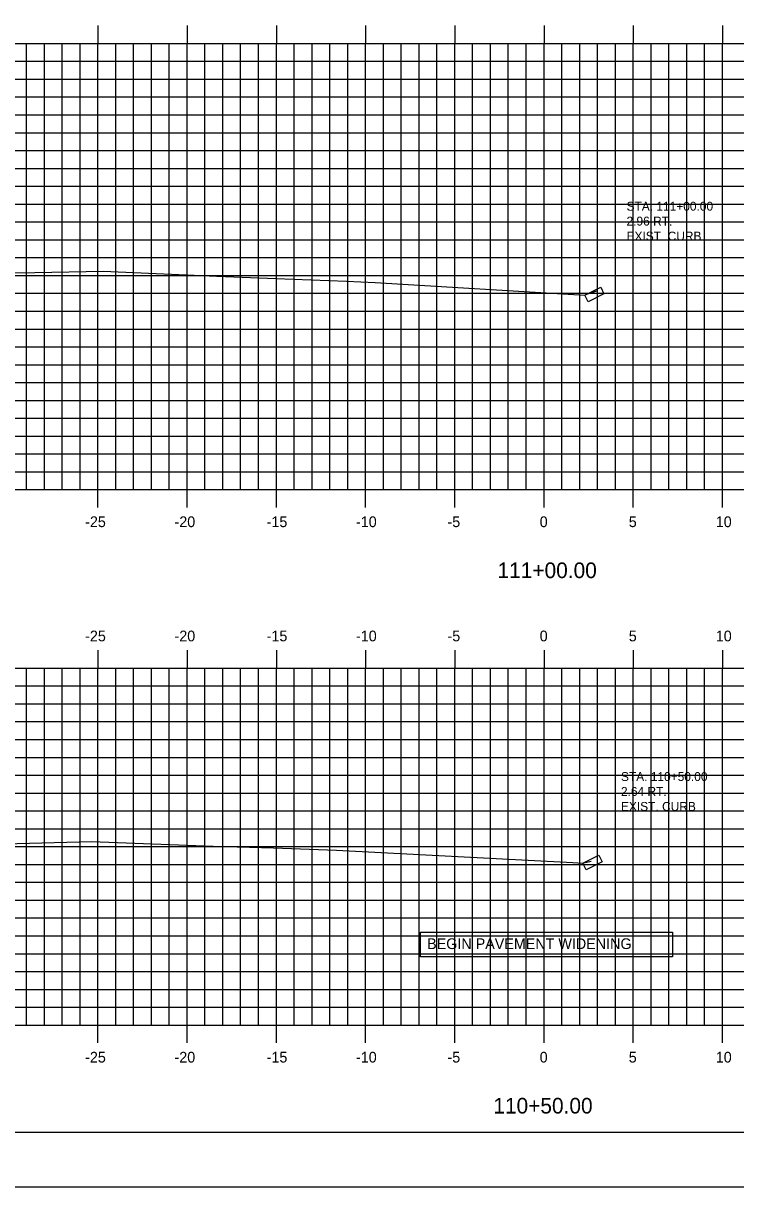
# Model space of a CAD drawing. Extents: x 1668473 to 1668643, y 337823 to 337933.
# Drawn here: x 1668526.6 to 1668566.5, y 337823.4 to 337888.6 of the extents above; entities that cross this region are included whole.
import ezdxf

# ---------------------------------------------------------------- set-up
doc = ezdxf.new("R2010")
doc.units = 0
for name, color, linetype in [('ANNOTATION', 7, 'Continuous'), ('BORDER', 7, 'Continuous'), ('D_Text_Monospaced', 7, 'Continuous'), ('H_V ANNOTATION', 7, 'Continuous'), ('MAJOR', 7, 'Continuous'), ('MINOR', 7, 'Continuous'), ('PLOT BOUNDARY', 7, 'Continuous'), ('S_Curb_Type_5', 7, 'Continuous'), ('S_Roadway_Centerline', 7, 'Continuous')]:
    doc.layers.add(name, color=color, linetype=linetype)

msp = doc.modelspace()

# ---------------------------------------------------------------- linework, layer by layer
at = {"layer": 'ANNOTATION'}
msp.add_lwpolyline([(1668548.868, 337837.666), (1668562.977, 337837.666), (1668562.977, 337836.276), (1668548.868, 337836.276)], close=True, dxfattribs=at)
at = {"layer": 'BORDER'}
msp.add_line((1668480.786, 337826.453), (1668640.786, 337826.453), dxfattribs=at)
at = {"layer": 'MAJOR'}
for p, q in [((1668530.785, 337888.455), (1668530.785, 337887.453)), ((1668535.785, 337888.455), (1668535.785, 337887.453)), ((1668540.785, 337888.455), (1668540.785, 337887.453)), ((1668545.785, 337888.455), (1668545.785, 337887.453)), ((1668550.785, 337888.455), (1668550.785, 337887.453)), ((1668555.785, 337888.455), (1668555.785, 337887.453)), ((1668560.785, 337888.455), (1668560.785, 337887.453)), ((1668565.785, 337888.455), (1668565.785, 337887.453)), ((1668485.785, 337887.453), (1668625.785, 337887.453)), ((1668485.785, 337887.453), (1668625.785, 337887.453)), ((1668530.785, 337862.453), (1668530.785, 337887.453)), ((1668535.785, 337862.453), (1668535.785, 337887.453)), ((1668540.785, 337862.453), (1668540.785, 337887.453)), ((1668545.785, 337862.453), (1668545.785, 337887.453)), ((1668550.785, 337862.453), (1668550.785, 337887.453)), ((1668555.785, 337862.453), (1668555.785, 337887.453)), ((1668560.785, 337862.453), (1668560.785, 337887.453)), ((1668565.785, 337862.453), (1668565.785, 337887.453)), ((1668485.785, 337882.453), (1668625.785, 337882.453)), ((1668485.785, 337877.453), (1668625.785, 337877.453)), ((1668485.785, 337872.453), (1668625.785, 337872.453)), ((1668485.785, 337867.453), (1668625.785, 337867.453)), ((1668485.785, 337862.453), (1668625.785, 337862.453)), ((1668485.785, 337862.453), (1668625.785, 337862.453)), ((1668530.785, 337861.451), (1668530.785, 337862.453)), ((1668535.785, 337861.451), (1668535.785, 337862.453)), ((1668540.785, 337861.451), (1668540.785, 337862.453)), ((1668545.785, 337861.451), (1668545.785, 337862.453)), ((1668550.785, 337861.451), (1668550.785, 337862.453)), ((1668555.785, 337861.451), (1668555.785, 337862.453)), ((1668560.785, 337861.451), (1668560.785, 337862.453)), ((1668565.785, 337861.451), (1668565.785, 337862.453)), ((1668530.785, 337853.455), (1668530.785, 337852.453)), ((1668535.785, 337853.455), (1668535.785, 337852.453)), ((1668540.785, 337853.455), (1668540.785, 337852.453)), ((1668545.785, 337853.455), (1668545.785, 337852.453)), ((1668550.785, 337853.455), (1668550.785, 337852.453)), ((1668555.785, 337853.455), (1668555.785, 337852.453)), ((1668560.785, 337853.455), (1668560.785, 337852.453)), ((1668565.785, 337853.455), (1668565.785, 337852.453)), ((1668485.785, 337852.453), (1668625.785, 337852.453)), ((1668485.785, 337852.453), (1668625.785, 337852.453)), ((1668530.785, 337832.453), (1668530.785, 337852.453)), ((1668535.785, 337832.453), (1668535.785, 337852.453)), ((1668540.785, 337832.453), (1668540.785, 337852.453)), ((1668545.785, 337832.453), (1668545.785, 337852.453)), ((1668550.785, 337832.453), (1668550.785, 337852.453)), ((1668555.785, 337832.453), (1668555.785, 337852.453)), ((1668560.785, 337832.453), (1668560.785, 337852.453)), ((1668565.785, 337832.453), (1668565.785, 337852.453)), ((1668485.785, 337847.453), (1668625.785, 337847.453)), ((1668485.785, 337842.453), (1668625.785, 337842.453)), ((1668485.785, 337837.453), (1668625.785, 337837.453)), ((1668485.785, 337832.453), (1668625.785, 337832.453)), ((1668485.785, 337832.453), (1668625.785, 337832.453)), ((1668530.785, 337831.451), (1668530.785, 337832.453)), ((1668535.785, 337831.451), (1668535.785, 337832.453)), ((1668540.785, 337831.451), (1668540.785, 337832.453)), ((1668545.785, 337831.451), (1668545.785, 337832.453)), ((1668550.785, 337831.451), (1668550.785, 337832.453)), ((1668555.785, 337831.451), (1668555.785, 337832.453)), ((1668560.785, 337831.451), (1668560.785, 337832.453)), ((1668565.785, 337831.451), (1668565.785, 337832.453))]:
    msp.add_line(p, q, dxfattribs=at)
at = {"layer": 'MINOR'}
for p, q in [((1668526.785, 337862.453), (1668526.785, 337887.453)), ((1668527.785, 337862.453), (1668527.785, 337887.453)), ((1668528.785, 337862.453), (1668528.785, 337887.453)), ((1668529.785, 337862.453), (1668529.785, 337887.453)), ((1668531.785, 337862.453), (1668531.785, 337887.453)), ((1668532.785, 337862.453), (1668532.785, 337887.453)), ((1668533.785, 337862.453), (1668533.785, 337887.453)), ((1668534.785, 337862.453), (1668534.785, 337887.453)), ((1668536.785, 337862.453), (1668536.785, 337887.453)), ((1668537.785, 337862.453), (1668537.785, 337887.453)), ((1668538.785, 337862.453), (1668538.785, 337887.453)), ((1668539.785, 337862.453), (1668539.785, 337887.453)), ((1668541.785, 337862.453), (1668541.785, 337887.453)), ((1668542.785, 337862.453), (1668542.785, 337887.453)), ((1668543.785, 337862.453), (1668543.785, 337887.453)), ((1668544.785, 337862.453), (1668544.785, 337887.453)), ((1668546.785, 337862.453), (1668546.785, 337887.453)), ((1668547.785, 337862.453), (1668547.785, 337887.453)), ((1668548.785, 337862.453), (1668548.785, 337887.453)), ((1668549.785, 337862.453), (1668549.785, 337887.453)), ((1668551.785, 337862.453), (1668551.785, 337887.453)), ((1668552.785, 337862.453), (1668552.785, 337887.453)), ((1668553.785, 337862.453), (1668553.785, 337887.453)), ((1668554.785, 337862.453), (1668554.785, 337887.453)), ((1668556.785, 337862.453), (1668556.785, 337887.453)), ((1668557.785, 337862.453), (1668557.785, 337887.453)), ((1668558.785, 337862.453), (1668558.785, 337887.453)), ((1668559.785, 337862.453), (1668559.785, 337887.453)), ((1668561.785, 337862.453), (1668561.785, 337887.453)), ((1668562.785, 337862.453), (1668562.785, 337887.453)), ((1668563.785, 337862.453), (1668563.785, 337887.453)), ((1668564.785, 337862.453), (1668564.785, 337887.453)), ((1668485.785, 337886.453), (1668625.785, 337886.453)), ((1668485.785, 337885.453), (1668625.785, 337885.453)), ((1668485.785, 337884.453), (1668625.785, 337884.453)), ((1668485.785, 337883.453), (1668625.785, 337883.453)), ((1668485.785, 337881.453), (1668625.785, 337881.453)), ((1668485.785, 337880.453), (1668625.785, 337880.453)), ((1668485.785, 337879.453), (1668625.785, 337879.453)), ((1668485.785, 337878.453), (1668625.785, 337878.453)), ((1668485.785, 337876.453), (1668625.785, 337876.453)), ((1668485.785, 337875.453), (1668625.785, 337875.453)), ((1668485.785, 337874.453), (1668625.785, 337874.453)), ((1668485.785, 337873.453), (1668625.785, 337873.453)), ((1668485.785, 337871.453), (1668625.785, 337871.453)), ((1668485.785, 337870.453), (1668625.785, 337870.453)), ((1668485.785, 337869.453), (1668625.785, 337869.453)), ((1668485.785, 337868.453), (1668625.785, 337868.453)), ((1668485.785, 337866.453), (1668625.785, 337866.453)), ((1668485.785, 337865.453), (1668625.785, 337865.453)), ((1668485.785, 337864.453), (1668625.785, 337864.453)), ((1668485.785, 337863.453), (1668625.785, 337863.453)), ((1668526.785, 337832.453), (1668526.785, 337852.453)), ((1668527.785, 337832.453), (1668527.785, 337852.453)), ((1668528.785, 337832.453), (1668528.785, 337852.453)), ((1668529.785, 337832.453), (1668529.785, 337852.453)), ((1668531.785, 337832.453), (1668531.785, 337852.453)), ((1668532.785, 337832.453), (1668532.785, 337852.453)), ((1668533.785, 337832.453), (1668533.785, 337852.453)), ((1668534.785, 337832.453), (1668534.785, 337852.453)), ((1668536.785, 337832.453), (1668536.785, 337852.453)), ((1668537.785, 337832.453), (1668537.785, 337852.453)), ((1668538.785, 337832.453), (1668538.785, 337852.453)), ((1668539.785, 337832.453), (1668539.785, 337852.453)), ((1668541.785, 337832.453), (1668541.785, 337852.453)), ((1668542.785, 337832.453), (1668542.785, 337852.453)), ((1668543.785, 337832.453), (1668543.785, 337852.453)), ((1668544.785, 337832.453), (1668544.785, 337852.453)), ((1668546.785, 337832.453), (1668546.785, 337852.453)), ((1668547.785, 337832.453), (1668547.785, 337852.453)), ((1668548.785, 337832.453), (1668548.785, 337852.453)), ((1668549.785, 337832.453), (1668549.785, 337852.453)), ((1668551.785, 337832.453), (1668551.785, 337852.453)), ((1668552.785, 337832.453), (1668552.785, 337852.453)), ((1668553.785, 337832.453), (1668553.785, 337852.453)), ((1668554.785, 337832.453), (1668554.785, 337852.453)), ((1668556.785, 337832.453), (1668556.785, 337852.453)), ((1668557.785, 337832.453), (1668557.785, 337852.453)), ((1668558.785, 337832.453), (1668558.785, 337852.453)), ((1668559.785, 337832.453), (1668559.785, 337852.453)), ((1668561.785, 337832.453), (1668561.785, 337852.453)), ((1668562.785, 337832.453), (1668562.785, 337852.453)), ((1668563.785, 337832.453), (1668563.785, 337852.453)), ((1668564.785, 337832.453), (1668564.785, 337852.453)), ((1668485.785, 337851.453), (1668625.785, 337851.453)), ((1668485.785, 337850.453), (1668625.785, 337850.453)), ((1668485.785, 337849.453), (1668625.785, 337849.453)), ((1668485.785, 337848.453), (1668625.785, 337848.453)), ((1668485.785, 337846.453), (1668625.785, 337846.453)), ((1668485.785, 337845.453), (1668625.785, 337845.453)), ((1668485.785, 337844.453), (1668625.785, 337844.453)), ((1668485.785, 337843.453), (1668625.785, 337843.453)), ((1668485.785, 337841.453), (1668625.785, 337841.453)), ((1668485.785, 337840.453), (1668625.785, 337840.453)), ((1668485.785, 337839.453), (1668625.785, 337839.453)), ((1668485.785, 337838.453), (1668625.785, 337838.453)), ((1668485.785, 337836.453), (1668625.785, 337836.453)), ((1668485.785, 337835.453), (1668625.785, 337835.453)), ((1668485.785, 337834.453), (1668625.785, 337834.453)), ((1668485.785, 337833.453), (1668625.785, 337833.453))]:
    msp.add_line(p, q, dxfattribs=at)
at = {"layer": 'PLOT BOUNDARY'}
msp.add_lwpolyline([(1668472.692, 337823.394), (1668642.692, 337823.394), (1668642.692, 337933.394), (1668472.692, 337933.394)], close=True, dxfattribs=at)
at = {"layer": 'S_Curb_Type_5'}
for points in [[(1668558.065, 337873.352), (1668558.96, 337873.799), (1668559.146, 337873.426), (1668558.252, 337872.979)], [(1668557.967, 337841.525), (1668558.861, 337841.972), (1668559.047, 337841.6), (1668558.153, 337841.152)]]:
    msp.add_lwpolyline(points, close=True, dxfattribs=at)
at = {"layer": 'S_Roadway_Centerline'}
for points in [[(1668485.785, 337878.938), (1668490.166, 337878.346), (1668499.66, 337873.584), (1668504.205, 337871.522), (1668504.935, 337871.161), (1668507.428, 337869.795), (1668507.872, 337870.059), (1668510.53, 337871.031), (1668515.69, 337872.791), (1668520.673, 337874.519), (1668527.258, 337874.625), (1668531.072, 337874.69), (1668537.457, 337874.418), (1668540.753, 337874.279), (1668544.714, 337874.138), (1668546.319, 337874.058), (1668558.065, 337873.352), (1668558.127, 337873.381), (1668558.744, 337873.584)], [(1668485.785, 337847.299), (1668495.054, 337843.171), (1668503.126, 337839.741), (1668505.839, 337838.397), (1668506.61, 337838.053), (1668507.011, 337838.248), (1668508.574, 337839.174), (1668512.971, 337840.378), (1668515.919, 337841.328), (1668519.521, 337842.472), (1668522.777, 337842.534), (1668530.425, 337842.737), (1668537.241, 337842.485), (1668540.634, 337842.378), (1668544.16, 337842.247), (1668557.408, 337841.56), (1668557.967, 337841.525), (1668557.994, 337841.538), (1668558.009, 337841.542), (1668558.43, 337841.629)]]:
    msp.add_lwpolyline(points, dxfattribs=at)

# ---------------------------------------------------------------- texts
at = {"layer": 'ANNOTATION'}
for s, height, p in [('C', 0.0146, (1668544.709, 337874.138)), ('L', 0.0146, (1668544.714, 337874.131)), ('C', 0.0146, (1668544.154, 337842.247)), ('L', 0.0146, (1668544.16, 337842.24)), ('BEGIN PAVEMENT WIDENING', 0.6, (1668549.235, 337836.712))]:
    msp.add_text(s, height=height, dxfattribs=at).set_placement(p)
at = {"layer": 'D_Text_Monospaced'}
for s, height, p in [('STA. 111+00.00', 0.49998, (1668560.41, 337878.082)), ('2.96 RT.', 0.5, (1668560.41, 337877.248)), ('EXIST. CURB', 0.49998, (1668560.41, 337876.408)), ('STA. 110+50.00', 0.49998, (1668560.097, 337846.127)), ('2.64 RT.', 0.5, (1668560.097, 337845.293)), ('EXIST. CURB', 0.49998, (1668560.097, 337844.453))]:
    msp.add_text(s, height=height, dxfattribs=at).set_placement(p)
at = {"layer": 'H_V ANNOTATION'}
for s, height, p in [('-25', 0.6, (1668530.071, 337860.353)), ('-20', 0.6, (1668535.079, 337860.353)), ('-15', 0.6, (1668540.242, 337860.353)), ('-10', 0.6, (1668545.25, 337860.353)), ('-5', 0.6, (1668550.376, 337860.353)), ('0', 0.6, (1668555.544, 337860.353)), ('5', 0.6, (1668560.536, 337860.353)), ('10', 0.6, (1668565.411, 337860.353)), ('111+00.00', 0.875, (1668553.18, 337857.497)), ('-25', 0.6, (1668530.071, 337853.953)), ('-20', 0.6, (1668535.079, 337853.953)), ('-15', 0.6, (1668540.242, 337853.953)), ('-10', 0.6, (1668545.25, 337853.953)), ('-5', 0.6, (1668550.376, 337853.953)), ('0', 0.6, (1668555.544, 337853.953)), ('5', 0.6, (1668560.536, 337853.953)), ('10', 0.6, (1668565.411, 337853.953)), ('-25', 0.6, (1668530.071, 337830.353)), ('-20', 0.6, (1668535.079, 337830.353)), ('-15', 0.6, (1668540.242, 337830.353)), ('-10', 0.6, (1668545.25, 337830.353)), ('-5', 0.6, (1668550.376, 337830.353)), ('0', 0.6, (1668555.544, 337830.353)), ('5', 0.6, (1668560.536, 337830.353)), ('10', 0.6, (1668565.411, 337830.353)), ('110+50.00', 0.875, (1668552.945, 337827.497))]:
    msp.add_text(s, height=height, dxfattribs=at).set_placement(p)

doc.saveas('drawing.dxf')
